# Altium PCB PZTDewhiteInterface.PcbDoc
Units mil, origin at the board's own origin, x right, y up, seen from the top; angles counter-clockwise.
Board outline 8000 x 1250 mil, 2 copper layers (Top Layer, Bottom Layer); 15 components, 53 nets, 135 pads, 0 vias.
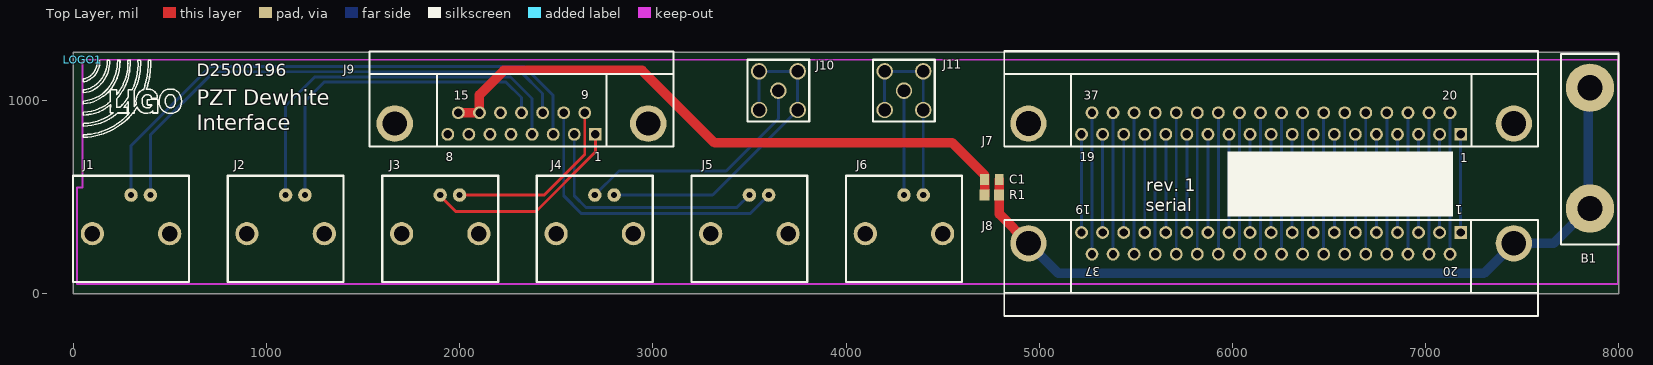
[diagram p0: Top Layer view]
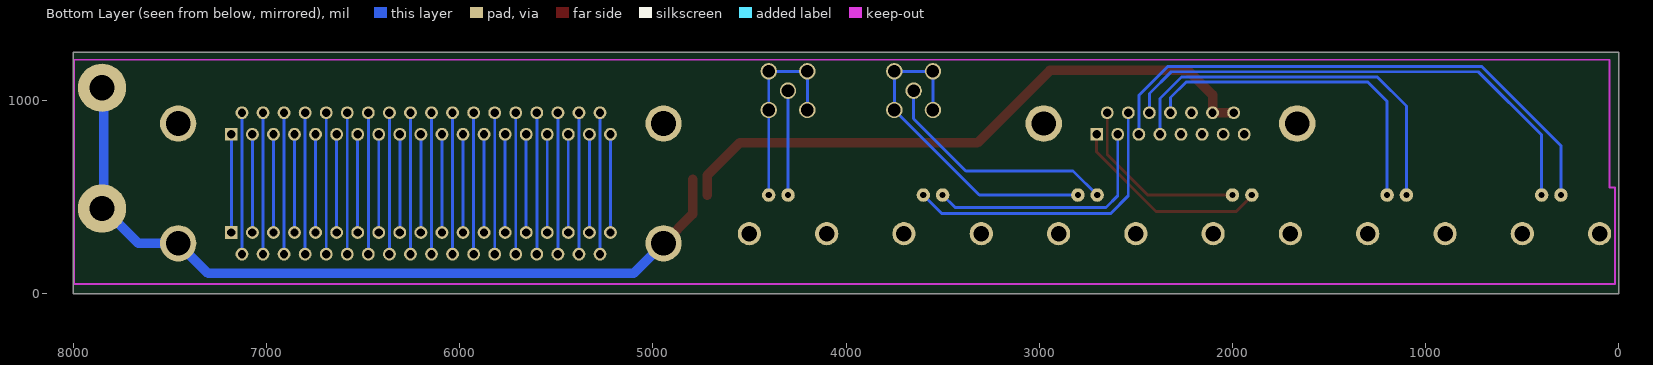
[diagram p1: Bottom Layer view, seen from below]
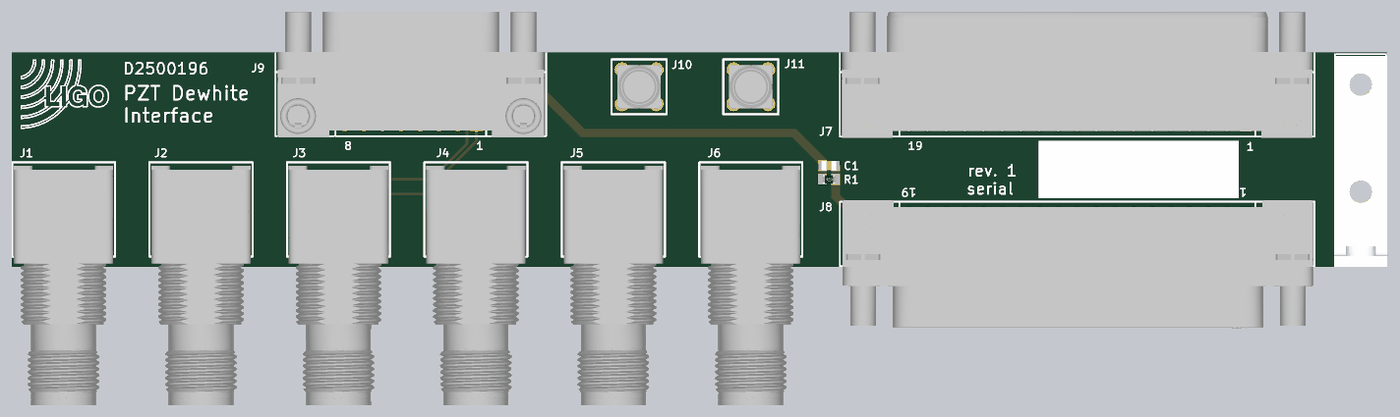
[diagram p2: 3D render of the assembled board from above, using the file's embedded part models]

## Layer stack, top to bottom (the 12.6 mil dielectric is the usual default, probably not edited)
Top Solder: solder mask 0.4, Solder Resist, Dk 3.5
Top Layer: signal copper 1.4
Dielectric 1: dielectric 12.6, FR-4, Dk 4.8
Bottom Layer: signal copper 1.4
Bottom Solder: solder mask 0.4, Solder Resist, Dk 3.5

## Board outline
0,0 0,1250 8000,1250 8000,0

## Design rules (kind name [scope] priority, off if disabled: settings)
Clearance [All] p1: gap=12 ignorepadtopadclearanceinfootprint=FALSE
HoleSize [All] p1: absolutevalues=TRUE maxlimit=150 minlimit=10 maxpercent=80.000 minpercent=20.000
MinimumAnnularRing [All] p1: minimumring=10
PolygonConnect [All] p1: connectstyle=Relief reliefconductorwidth=10 reliefentries=4 polygonreliefangle="90 Angle" airgapwidth=10
RoutingVias [All] p1: holewidth=15 width=50 viastyle="Through Hole" minholewidth=10 minwidth=25 maxholewidth=28 maxwidth=35
SolderMaskExpansion [All] p1: expansion=4 istentingtop=FALSE
SupplyNets "Schematic Supply Nets" [InNet('GND')] p1: voltage=0.000
Width [All] p1: maxlimit=100 minlimit=10 preferedwidth=15
29 further rules are at their usual default settings.

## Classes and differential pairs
component class PZTDewhiteInterface1: B1 C1 J1 J2 J3 J4 J5 J6 J7 J8 J10 J11 LOGO1 R1

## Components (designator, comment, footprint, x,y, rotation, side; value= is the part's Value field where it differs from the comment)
B1 "Bracket" Bracket-RA_708 7850,440 r0 top locked
C1 "1u" CC2013-0805 4755,590 r180 top
J1 "TNC" TNC2 300,50 r180 top
J2 "TNC" TNC2 1100,50 r180 top
J3 "TNC" TNC2 1900,50 r180 top
J4 "TNC" TNC2 2700,50 r180 top
J5 "TNC" TNC2 3500,50 r180 top
J6 "TNC" TNC2 4300,50 r180 top
J7 "DB37M" DB37M-RA 6200,880 r0 top
J8 "DB37F" DB37F-RA 6200,260 r180 top
J9 "DB15M" DB15M-RA 2321,880 r0 top
J10 "SMA" SMA 3650,1050 r0 top
J11 "SMA" SMA 4300,1050 r0 top
LOGO1 "LIGO logo" LIGO_LOGO 50,1210 r0 top
R1 "NL" CR2012-0805 4755,510 r180 top

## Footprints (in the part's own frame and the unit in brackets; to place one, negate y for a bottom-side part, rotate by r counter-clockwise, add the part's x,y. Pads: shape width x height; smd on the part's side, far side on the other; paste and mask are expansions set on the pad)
Bracket-RA_708 [mil] "Keystone Electronics right-angle 6-32 steel, 708"
  round 250 hole 130: 1(0,0) 2(0,625)
  silkscreen extent -150,-187 148,800, body extent -156,-439 156,791, height 390
CC2013-0805 [mm] "Chip Capacitor; Body 2.0 x 1.3 mm (LxW typ)"
  rect 1.15x1.4 smd: 1(-0.975,0) 2(0.975,0)
  body extent -1.1,-0.72 1.1,0.73, height 0.88
CR2012-0805 [mm] "Chip Resistor; Body 2.0 x 1.3 mm (LxW typ)"
  rect 1.3x1.5 smd: 1(-0.95,0) 2(0.95,0)
  body extent -1,-0.62 1,0.63, height 0.46
DB15M-RA [mm] "Plug; D Subminiature 15 Position; Right Angle"
  rect 1.69x1.69 hole 1.09: 1(9.695,-1.42)
  round 1.69 hole 1.09: 2(6.925,-1.42) 3(4.155,-1.42) 4(1.385,-1.42) 5(-1.385,-1.42) 6(-4.155,-1.42) 7(-6.925,-1.42) 8(-9.695,-1.42) 9(8.31,1.42) 10(5.54,1.42) 11(2.77,1.42) 12(0,1.42) 13(-2.77,1.42) 14(-5.54,1.42) 15(-8.31,1.42)
  round 4.8 hole 3.18: 16(16.66,0) 17(-16.66,0)
  silkscreen extent -20,-3 20,9.5, body extent -19.68,-3.2 19.68,15.4, height 12.62
DB37F-RA [mm] "Receptiacle; D Subminiature 37 Position; Right Angle"
  rect 1.69x1.69 hole 1.09: 1(-24.917,-1.42)
  round 1.69 hole 1.09: 2(-22.149,-1.42) 3(-19.38,-1.42) 4(-16.612,-1.42) 5(-13.843,-1.42) 6(-11.074,-1.42) 7(-8.306,-1.42) 8(-5.537,-1.42) 9(-2.769,-1.42) 10(0,-1.42) 11(2.769,-1.42) 12(5.537,-1.42) 13(8.306,-1.42) 14(11.074,-1.42) 15(13.843,-1.42) 16(16.612,-1.42) 17(19.38,-1.42) 18(22.149,-1.42) 19(24.917,-1.42) 20(-23.52,1.42) 21(-20.752,1.42) 22(-17.983,1.42) 23(-15.215,1.42) 24(-12.446,1.42) 25(-9.677,1.42) 26(-6.909,1.42) 27(-4.14,1.42) 28(-1.372,1.42) 29(1.397,1.42) 30(4.166,1.42) 31(6.934,1.42) 32(9.703,1.42) 33(12.471,1.42) 34(15.24,1.42) 35(18.009,1.42) 36(20.777,1.42) 37(23.546,1.42)
  round 4.76 hole 3.26: 38(-31.902,0) 39(31.902,0)
  silkscreen extent -35.08,-3.05 35.08,9.52, body extent -34.87,-3.25 34.67,15.68, height 12.62
DB37M-RA [mm] "Plug; D Subminiature 37 Position; Right Angle"
  rect 1.69x1.69 hole 1.09: 1(24.917,-1.42)
  round 1.69 hole 1.09: 2(22.149,-1.42) 3(19.38,-1.42) 4(16.612,-1.42) 5(13.843,-1.42) 6(11.074,-1.42) 7(8.306,-1.42) 8(5.537,-1.42) 9(2.769,-1.42) 10(0,-1.42) 11(-2.769,-1.42) 12(-5.537,-1.42) 13(-8.306,-1.42) 14(-11.074,-1.42) 15(-13.843,-1.42) 16(-16.612,-1.42) 17(-19.38,-1.42) 18(-22.149,-1.42) 19(-24.917,-1.42) 20(23.52,1.42) 21(20.752,1.42) 22(17.983,1.42) 23(15.215,1.42) 24(12.446,1.42) 25(9.677,1.42) 26(6.909,1.42) 27(4.14,1.42) 28(1.372,1.42) 29(-1.397,1.42) 30(-4.166,1.42) 31(-6.934,1.42) 32(-9.703,1.42) 33(-12.471,1.42) 34(-15.24,1.42) 35(-18.009,1.42) 36(-20.777,1.42) 37(-23.546,1.42)
  round 4.76 hole 3.26: 38(31.902,0) 39(-31.902,0)
  silkscreen extent -35.08,-3.05 35.08,9.52, body extent -34.77,-3.24 34.77,15.37, height 12.62
LIGO_LOGO [mil] "LIGO logo"
  silkscreen extent 3,-402 511,-3
SMA [mil] "SMA straight PCB"
  round 85 hole 65: 1(0,0) 2(-100,-100) 2(-100,100) 2(100,-100) 2(100,100)
  silkscreen extent -160,-160 160,160, body extent -126,-126 126,126, height 370
TNC2 [mil] "TNC right angle PCB"
  round 70 hole 32: 1(0,-460) 2(-100,-460)
  round 120 hole 80: 3(-200,-260) 4(200,-260)
  silkscreen extent -300,-560 300,-10, body extent -289,-540 289,858, height 623

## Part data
B1: library part Bracket_708, "Keystone Electronics right-angle 6-32 steel, 708", Part Number=36-708-ND
C1: library part ChipCap, "Capacitor, surface mount", Part Number=1276-2928-1-ND, Tolerance=10%
J1 J2 J3 J4 J5 J6: library part BNC, "TNC, PCB Mount, Right Angle", Part Number=A32444-ND
J7: "Plug Assembly, 37 Position, Right Angle, .318 Series", Part Number=5747843-2-ND
J8: "Receptacle Assembly, 37 Position, Right Angle, .318 Series", Part Number=A32130-ND
J9: "Plug Assembly, 15 Position, Right Angle, .318 Series", Part Number=609-6495-ND
J10 J11: "SMA, PCB Mount, Straight", Part Number=900-0732517040-ND
LOGO1: library part LIGO_logo
R1: library part ChipRes1, "Resistor, surface mount", Tolerance=1%

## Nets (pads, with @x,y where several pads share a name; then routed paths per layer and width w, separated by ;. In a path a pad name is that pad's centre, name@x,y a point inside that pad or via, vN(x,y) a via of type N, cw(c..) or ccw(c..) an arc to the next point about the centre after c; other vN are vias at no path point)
0Va: J7.1 J8.1 | length 508.1
  Bottom Layer w15: J8.1 7181,569.95 J7.1@7181,824
0Vb: J7.20 J8.20 | length 731.9
  Bottom Layer w15: J8.20@7125.91,204.09 7125.91,570 ; J7.20@7125.91,935.91 7125.91,570 ; 7125.95,569.95 7125.91,570
"+15 Led": J9.6
+15a: J7.18 J8.18 | length 508.2
  Bottom Layer w15: 5328.05,570 5328.09,569.95 ; J8.18@5328.09,315.91 5328.09,569.95 ; J7.18@5328.09,824 5328.09,569.95
+15b: J7.37 J8.37 | length 731.8
  Bottom Layer w15: J8.37 5273,570 J7.37
"-15 Led": J9.7
BI_0: J7.2 J8.2 | length 508.1
  Bottom Layer w15: J8.2 J7.2@7072,824
BI_1: J7.3 J8.3 | length 508.1
  Bottom Layer w15: J8.3 J7.3@6963,824
BI_2: J7.4 J8.4 | length 508.1
  Bottom Layer w15: J8.4 J7.4@6854,824
BI_3: J7.5 J8.5 | length 508.1
  Bottom Layer w15: J8.5 J7.5@6745,824
BI_4: J7.6 J8.6 | length 508.1
  Bottom Layer w15: J8.6 J7.6@6636,824
BI_5: J7.7 J8.7 | length 508.1
  Bottom Layer w15: J8.7 J7.7@6527,824
BI_6: J7.8 J8.8 | length 508.1
  Bottom Layer w15: J8.8 J7.8@6418,824
BI_7: J7.9 J8.9 | length 508.1
  Bottom Layer w15: J8.9 J7.9@6309,824
BI_8: J7.10 J8.10 | length 508.1
  Bottom Layer w15: J8.10 J7.10@6200,824
BI_9: J7.11 J8.11 | length 508.1
  Bottom Layer w15: J8.11 J7.11@6091,824
BI_10: J7.12 J8.12 | length 508.1
  Bottom Layer w15: J8.12 J7.12@5982,824
BI_11: J7.13 J8.13 | length 508.1
  Bottom Layer w15: J8.13 J7.13@5873,824
BI_12: J7.14 J8.14 | length 508.1
  Bottom Layer w15: J8.14 J7.14@5764,824
BI_13: J7.15 J8.15 | length 508.1
  Bottom Layer w15: J8.15 J7.15@5655,824
BI_14: J7.16 J8.16 | length 508.1
  Bottom Layer w15: J8.16@5546.09,315.91 J7.16@5546.09,824
BI_15: J7.17 J8.17 | length 508.1
  Bottom Layer w15: J8.17@5437.09,315.91 J7.17@5437.09,824
BI_16: J7.21 J8.21 | length 731.8
  Bottom Layer w15: J8.21@7016.91,204.09 J7.21@7016.91,935.91
BI_17: J7.22 J8.22 | length 731.8
  Bottom Layer w15: J8.22@6907.91,204.09 J7.22@6907.91,935.91
BI_18: J7.23 J8.23 | length 731.8
  Bottom Layer w15: J8.23@6798.91,204.09 J7.23@6798.91,935.91
BI_19: J7.24 J8.24 | length 731.8
  Bottom Layer w15: J8.24@6689.91,204.09 J7.24@6689.91,935.91
BI_20: J7.25 J8.25 | length 731.8
  Bottom Layer w15: J8.25@6580.91,204.09 J7.25@6580.91,935.91
BI_21: J7.26 J8.26 | length 731.8
  Bottom Layer w15: J8.26@6471.91,204.09 J7.26@6471.91,935.91
BI_22: J7.27 J8.27 | length 731.8
  Bottom Layer w15: J8.27@6362.91,204.09 J7.27@6362.91,935.91
BI_23: J7.28 J8.28 | length 731.8
  Bottom Layer w15: J8.28@6253.91,204.09 J7.28@6253.91,935.91
BI_24: J7.29 J8.29 | length 731.8
  Bottom Layer w15: J8.29@6144.91,204.09 J7.29@6144.91,935.91
BI_25: J7.30 J8.30 | length 731.8
  Bottom Layer w15: J8.30@6035.91,204.09 J7.30@6035.91,935.91
BI_26: J7.31 J8.31 | length 731.8
  Bottom Layer w15: J8.31@5926.91,204.09 J7.31@5926.91,935.91
BI_27: J7.32 J8.32 | length 731.8
  Bottom Layer w15: J8.32@5817.91,204.09 J7.32@5817.91,935.91
BI_28: J7.33 J8.33 | length 731.8
  Bottom Layer w15: J8.33@5708.91,204.09 J7.33@5708.91,935.91
BI_29: J7.34 J8.34 | length 731.8
  Bottom Layer w15: J8.34 J7.34
BI_30: J7.35 J8.35 | length 731.8
  Bottom Layer w15: J8.35 J7.35
BI_31: J7.36 J8.36 | length 731.8
  Bottom Layer w15: J8.36 J7.36
GND: C1.2 J9.14 J9.15 R1.2 | length 3195.6
  Top Layer w50: J9.15 J9.14 2102.89,1027.89 2230,1155 2945,1155 3320,780 4550,780 4717.6,612.4 4717.6,590 R1.2
IN1_N: J1.2 J9.11 | length 2621.8
  Bottom Layer w15: J1.2 400,820 728,1148 2317,1148 2430.05,1034.94 J9.11
IN1_P: J1.1 J9.3 | length 2872.7
  Bottom Layer w15: J1.1 300,765 710,1175 2335,1175 2484.58,1025.42 J9.3
IN2_N: J2.2 J9.12 | length 1758.2
  Bottom Layer w15: J2.2 1200,995 1299,1094 2241,1094 2321,1014 J9.12
IN2_P: J2.1 J9.4 | length 2029.6
  Bottom Layer w15: J2.1 1100,970 1251,1121 2264,1121 2375.53,1009.47 J9.4
IN3_N: J3.2 J9.9 | length 951.2
  Top Layer w15: J3.2 2438.41,510 2648.16,719.76 J9.9
IN3_P: J3.1 J9.1 | length 1059.7
  Top Layer w15: J3.1 1900,505 1980,425 2395,425 2702.69,732.69 J9.1
IN4_N: J5.2 J9.10 | length 1567.9
  Bottom Layer w15: J9.10 2539.11,505.89 2630,415 3505,415 J5.2
IN4_P: J5.1 J9.2 | length 1276.4
  Bottom Layer w15: J9.2 2593.64,506.36 2655,445 3435,445 J5.1
NetB1_1: B1.1 B1.2 C1.1 J8.38 J8.39 R1.1 | length 4118.4
  Top Layer w50: C1.1 4793.39,410.61 J8.39
  Bottom Layer w50: J8.39 5099,105 7301,105 J8.38 7662,260 7842,440 B1.2@7842,1065
NetJ7_19: J7.19 J8.19 | length 508.3
  Bottom Layer w15: J7.19 5219.09,824 J8.19@5219.09,315.91
  Bottom Layer w50: J8.19 J8.19@5219.09,315.91
OUT3_N: J4.2 J10.2 | length 1732.3
  Bottom Layer w15: J4.2 3310,510 3750,950 3750,1150 3550,1150 J10.2@3550,950
OUT3_P: J4.1 J10.1 | length 1258.6
  Bottom Layer w15: J4.1 2825,635 3380,635 3650,905 J10.1
OUT4_N: J6.2 J11.2 | length 1040
  Bottom Layer w15: J11.2@4200,950 4200,1150 4400,1150 4400,950 J6.2
OUT4_P: J6.1 J11.1 | length 540
  Bottom Layer w15: J6.1 J11.1
pads on no net: J1.3 J1.4 J2.3 J2.4 J3.3 J3.4 J4.3 J4.4 J5.3 J5.4 J6.3 J6.4 J7.38 J7.39 J9.5 J9.8 J9.13 J9.16 J9.17

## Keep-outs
Keep-Out Layer:
  lines w10: 20,50 20,550 50,550 50,1210 7995,1210 7995,50 20,50

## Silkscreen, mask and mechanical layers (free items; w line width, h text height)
Top Overlay:
  rectangle: 5975,400 7140,735
  text "D2500196" at 640,1125 h65
  text "PZT Dewhite" at 640,975 h80
  text "Interface" at 640,845 h80
  text "rev. 1" at 5555,530 h65
  text "serial" at 5550,425 h65
Mechanical 1:
  the board outline again, w10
